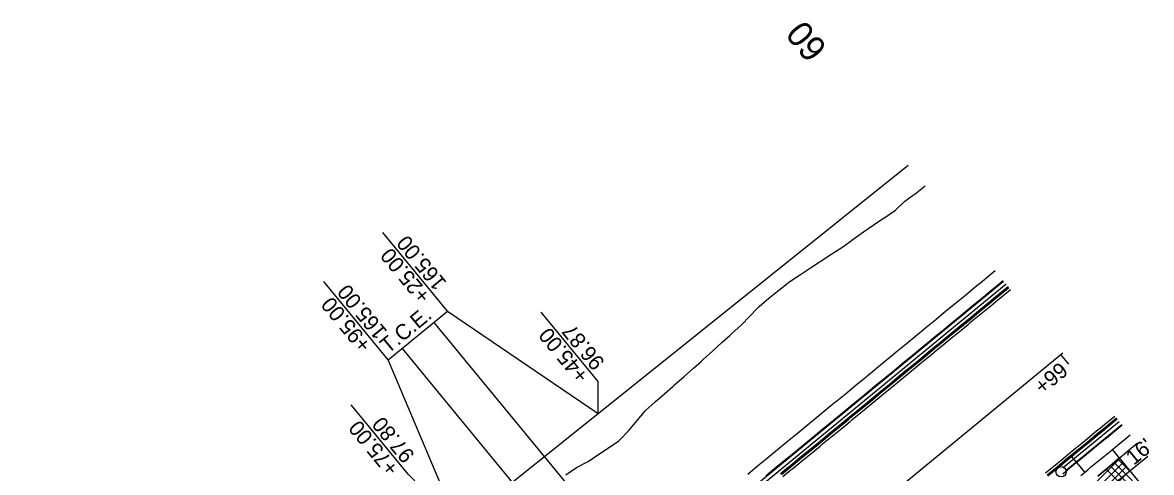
# Model space of a CAD drawing. Extents: x 1147550 to 1149124, y 2017436 to 2018779.
# Drawn here: x 1148677.5 to 1149118, y 2018603.7 to 2018779.4 of the extents above; entities that cross this region are included whole.
import ezdxf

# ---------------------------------------------------------------- set-up
doc = ezdxf.new("R2010")
doc.units = 0
for name, color, linetype in [('S_EDGE_CONCRETE', 7, 'Continuous'), ('S_HEADWALL', 7, 'Continuous'), ('S_IRON_PIN', 7, 'Continuous'), ('S_IRON_PIN_ANNOT', 7, 'Continuous'), ('S_LANDSCAPING', 7, 'Continuous'), ('S_MAILBOX', 7, 'Continuous'), ('S_RDW_PT_SYM', 7, 'Continuous'), ('S_SECONDARY_CTL', 7, 'Continuous'), ('S_TELEPHONE_UTILITIES', 7, 'Continuous'), ('S_TELEPHONE_UTILITIES_ANNOT', 7, 'Continuous')]:
    doc.layers.add(name, color=color, linetype=linetype)

msp = doc.modelspace()

# ---------------------------------------------------------------- linework, layer by layer
at = {"layer": 'S_EDGE_CONCRETE'}
msp.add_line((1148677.53, 2018316.54), (1149083.36, 2018650.43), dxfattribs=at)
at = {"layer": 'S_HEADWALL'}
for p, q in [((1148837.98, 2018662.21), (1148916.45, 2018566.84)), ((1148825.63, 2018652.05), (1148904.09, 2018556.68)), ((1149085.76, 2018645.93), (1149082.59, 2018649.79)), ((1149091.96, 2018603.77), (1149086.88, 2018609.94)), ((1149117.99, 2018594.17), (1149102.78, 2018612.66))]:
    msp.add_line(p, q, dxfattribs=at)
at = {"layer": 'S_IRON_PIN'}
msp.add_lwpolyline([(1148847.47, 2018583), (1148820.22, 2018647.6), (1148843.39, 2018666.66), (1148902.12, 2018626.75)], dxfattribs=at)
at = {"layer": 'S_IRON_PIN_ANNOT'}
for p, q in [((1148922.38, 2018425.84), (1149105.68, 2018609.13)), ((1149104.93, 2018608.83), (1149110.52, 2018603.24)), ((1148923.66, 2018424.29), (1149106.95, 2018607.58)), ((1148924.94, 2018422.74), (1149108.23, 2018606.03)), ((1148926.21, 2018421.18), (1149109.51, 2018604.48)), ((1149100.34, 2018604.95), (1149114.52, 2018590.76)), ((1149101.87, 2018606.24), (1149115.95, 2018592.16)), ((1149103.4, 2018607.54), (1149117.37, 2018593.57))]:
    msp.add_line(p, q, dxfattribs=at)
msp.add_lwpolyline([(1149117.96, 2018594.21), (1149105.52, 2018609.33), (1149100.94, 2018605.45), (1149097.12, 2018602.22)], dxfattribs=at)
at = {"layer": 'S_LANDSCAPING'}
for points in [[(1148843.39, 2018666.66), (1148818.14, 2018697.35)], [(1148820.22, 2018647.6), (1148795.02, 2018678.23)], [(1148902.12, 2018626.75), (1148902.12, 2018639.23), (1148879.88, 2018666.26)], [(1148847.47, 2018583), (1148827.96, 2018602.98), (1148805.73, 2018630.01)]]:
    msp.add_lwpolyline(points, dxfattribs=at)
at = {"layer": 'S_MAILBOX'}
msp.add_line((1148835.76, 2018573.62), (1149023.13, 2018723.63), dxfattribs=at)
msp.add_lwpolyline([(1149101.12, 2018597.36), (1149116.55, 2018610.09)], dxfattribs=at)
at = {"layer": 'S_SECONDARY_CTL'}
for points in [[(1148889.45, 2018602.8), (1148893.62, 2018605.6), (1148897.97, 2018607.87), (1148898.16, 2018607.96), (1148902.33, 2018610.75), (1148906.5, 2018613.56), (1148910.14, 2018616.08), (1148910.61, 2018616.44), (1148914.07, 2018620.1), (1148917.34, 2018624), (1148920.17, 2018627.38), (1148920.63, 2018627.86), (1148924.38, 2018631.18), (1148928.12, 2018634.5), (1148931.32, 2018637.33), (1148931.87, 2018637.82), (1148935.61, 2018641.14), (1148939.35, 2018644.45), (1148942.37, 2018647.16), (1148943.1, 2018647.77), (1148946.8, 2018651.14), (1148950.51, 2018654.5), (1148953.45, 2018657.17), (1148954.21, 2018657.87), (1148957.92, 2018661.24), (1148961.41, 2018664.86), (1148964.09, 2018667.7), (1148964.87, 2018668.53), (1148968.69, 2018671.76), (1148972.62, 2018674.85), (1148975.6, 2018677.18), (1148976.56, 2018677.93), (1148980.71, 2018680.75), (1148984.92, 2018683.51), (1148988.01, 2018685.56), (1148989.12, 2018686.28), (1148993.34, 2018689.01), (1148997.52, 2018691.81), (1149000.46, 2018693.91), (1149001.59, 2018694.72), (1149005.67, 2018697.63), (1149009.83, 2018700.45), (1149012.73, 2018702.47), (1149013.97, 2018703.28), (1149018.16, 2018706.06), (1149021.72, 2018709.61), (1149024.63, 2018711.69), (1149025.79, 2018712.52), (1149029.74, 2018715.6)], [(1149097.12, 2018602.22), (1149100.94, 2018605.45), (1149104.75, 2018608.68), (1149107.48, 2018610.99), (1149108.57, 2018611.91), (1149112.4, 2018615.13)]]:
    msp.add_lwpolyline(points, dxfattribs=at)
at = {"layer": 'S_TELEPHONE_UTILITIES'}
for points in [[(1148960.46, 2018603.06), (1148964.32, 2018606.23), (1148968.19, 2018609.41), (1148971.31, 2018611.98), (1148972.05, 2018612.59), (1148975.91, 2018615.76), (1148979.77, 2018618.94), (1148982.83, 2018621.46), (1148983.63, 2018622.12), (1148987.49, 2018625.29), (1148991.35, 2018628.47), (1148994.34, 2018630.93), (1148995.21, 2018631.65), (1148999.08, 2018634.82), (1149002.94, 2018638), (1149005.86, 2018640.4), (1149006.8, 2018641.18), (1149010.66, 2018644.35), (1149014.52, 2018647.53), (1149017.37, 2018649.88), (1149018.38, 2018650.71), (1149022.24, 2018653.88), (1149026.1, 2018657.06), (1149028.89, 2018659.36), (1149029.96, 2018660.24), (1149033.83, 2018663.41), (1149037.69, 2018666.59), (1149040.41, 2018668.83), (1149041.55, 2018669.77), (1149045.41, 2018672.94), (1149049.27, 2018676.12), (1149052.03, 2018678.39), (1149053.13, 2018679.3), (1149056.99, 2018682.47)], [(1148967.5, 2018602.37), (1148971.36, 2018605.55), (1148974.49, 2018608.12), (1148975.22, 2018608.73), (1148979.08, 2018611.9), (1148982.95, 2018615.08), (1148986.01, 2018617.6), (1148986.81, 2018618.26), (1148990.67, 2018621.43), (1148994.53, 2018624.61), (1148997.52, 2018627.07), (1148998.39, 2018627.79), (1149002.25, 2018630.96), (1149006.11, 2018634.14), (1149009.04, 2018636.54), (1149009.97, 2018637.32), (1149013.84, 2018640.49), (1149017.7, 2018643.67), (1149020.55, 2018646.02), (1149021.56, 2018646.85), (1149025.42, 2018650.02), (1149029.28, 2018653.2), (1149032.07, 2018655.49), (1149033.14, 2018656.38), (1149037, 2018659.55), (1149040.86, 2018662.73), (1149043.59, 2018664.97), (1149044.72, 2018665.91), (1149048.59, 2018669.08), (1149052.45, 2018672.26), (1149055.21, 2018674.53), (1149056.31, 2018675.44), (1149060.17, 2018678.61)], [(1148973.27, 2018603.23), (1148976.39, 2018605.8), (1148977.13, 2018606.41), (1148980.99, 2018609.59), (1148984.85, 2018612.76), (1148987.91, 2018615.28), (1148988.71, 2018615.94), (1148992.57, 2018619.12), (1148996.44, 2018622.29), (1148999.43, 2018624.75), (1149000.3, 2018625.47), (1149004.16, 2018628.65), (1149008.02, 2018631.82), (1149010.94, 2018634.23), (1149011.88, 2018635), (1149015.74, 2018638.18), (1149019.6, 2018641.35), (1149022.46, 2018643.7), (1149023.46, 2018644.53), (1149027.32, 2018647.71), (1149031.19, 2018650.88), (1149033.98, 2018653.18), (1149035.05, 2018654.06), (1149038.91, 2018657.24), (1149042.77, 2018660.41), (1149045.49, 2018662.65), (1149046.63, 2018663.59), (1149050.49, 2018666.77), (1149054.35, 2018669.94), (1149057.11, 2018672.21), (1149058.21, 2018673.12), (1149062.08, 2018676.3)], [(1148973.59, 2018602.85), (1148976.71, 2018605.42), (1148977.45, 2018606.02), (1148981.31, 2018609.2), (1148985.17, 2018612.38), (1148988.23, 2018614.89), (1148989.03, 2018615.55), (1148992.89, 2018618.73), (1148996.75, 2018621.91), (1148999.74, 2018624.37), (1149000.61, 2018625.08), (1149004.48, 2018628.26), (1149008.34, 2018631.44), (1149011.26, 2018633.84), (1149012.2, 2018634.61), (1149016.06, 2018637.79), (1149019.92, 2018640.97), (1149022.77, 2018643.31), (1149023.78, 2018644.14), (1149027.64, 2018647.32), (1149031.5, 2018650.5), (1149034.29, 2018652.79), (1149035.36, 2018653.67), (1149039.23, 2018656.85), (1149043.09, 2018660.03), (1149045.81, 2018662.27), (1149046.95, 2018663.2), (1149050.81, 2018666.38), (1149054.67, 2018669.56), (1149057.43, 2018671.83), (1149058.53, 2018672.73), (1149062.39, 2018675.91)], [(1148974.22, 2018602.07), (1148977.35, 2018604.65), (1148978.08, 2018605.25), (1148981.94, 2018608.43), (1148985.81, 2018611.6), (1148988.87, 2018614.12), (1148989.67, 2018614.78), (1148993.53, 2018617.96), (1148997.39, 2018621.13), (1149000.38, 2018623.6), (1149001.25, 2018624.31), (1149005.11, 2018627.49), (1149008.97, 2018630.66), (1149011.89, 2018633.07), (1149012.83, 2018633.84), (1149016.69, 2018637.02), (1149020.56, 2018640.19), (1149023.41, 2018642.54), (1149024.42, 2018643.37), (1149028.28, 2018646.55), (1149032.14, 2018649.72), (1149034.93, 2018652.02), (1149036, 2018652.9), (1149039.86, 2018656.08), (1149043.72, 2018659.25), (1149046.44, 2018661.49), (1149047.58, 2018662.43), (1149051.44, 2018665.61), (1149055.31, 2018668.78), (1149058.07, 2018671.05), (1149059.17, 2018671.96), (1149063.03, 2018675.14)], [(1149076.66, 2018603.48), (1149080.52, 2018606.65), (1149084.38, 2018609.83), (1149087.11, 2018612.07), (1149088.25, 2018613.01), (1149092.11, 2018616.18), (1149095.97, 2018619.36), (1149098.73, 2018621.63), (1149099.83, 2018622.54), (1149103.69, 2018625.71)], [(1149077.3, 2018602.71), (1149081.16, 2018605.88), (1149085.02, 2018609.06), (1149087.74, 2018611.3), (1149088.88, 2018612.24), (1149092.74, 2018615.41), (1149096.6, 2018618.59), (1149099.36, 2018620.86), (1149100.46, 2018621.77), (1149104.33, 2018624.94)], [(1149077.61, 2018602.32), (1149081.48, 2018605.5), (1149085.34, 2018608.67), (1149088.06, 2018610.91), (1149089.2, 2018611.85), (1149093.06, 2018615.03), (1149096.92, 2018618.2), (1149099.68, 2018620.47), (1149100.78, 2018621.38), (1149104.64, 2018624.56)], [(1149083.38, 2018603.18), (1149087.24, 2018606.36), (1149089.97, 2018608.6), (1149091.1, 2018609.53), (1149094.97, 2018612.71), (1149098.83, 2018615.89), (1149101.59, 2018618.16), (1149102.69, 2018619.06), (1149106.55, 2018622.24)], [(1149090.42, 2018602.5), (1149093.14, 2018604.73), (1149094.28, 2018605.67), (1149098.14, 2018608.85), (1149102, 2018612.03), (1149104.76, 2018614.3), (1149105.86, 2018615.2), (1149109.73, 2018618.38)]]:
    msp.add_lwpolyline(points, dxfattribs=at)
at = {"layer": 'S_TELEPHONE_UTILITIES_ANNOT'}
for p, q in [((1148876.42, 2018527.12), (1149060.33, 2018678.42)), ((1148876.42, 2018527.12), (1149060.33, 2018678.42)), ((1148877.38, 2018525.96), (1149061.28, 2018677.26)), ((1148877.38, 2018525.96), (1149061.28, 2018677.26)), ((1149083.7, 2018605.71), (1149105.44, 2018623.59)), ((1149083.7, 2018605.71), (1149105.44, 2018623.59)), ((1149084.66, 2018604.55), (1149106.39, 2018622.43)), ((1149084.66, 2018604.55), (1149106.39, 2018622.43))]:
    msp.add_line(p, q, dxfattribs=at)
msp.add_circle((1149082.75, 2018603.95), 2, dxfattribs=at)

# ---------------------------------------------------------------- texts
at = {"layer": 'S_HEADWALL'}
for s, p in [('+99', (1149075.46, 2018633.83)), ("16'", (1149111.08, 2018606.23))]:
    msp.add_text(s, height=6, rotation=39.4453, dxfattribs=at).set_placement(p)
at = {"layer": 'S_IRON_PIN'}
msp.add_text('T.C.E.', height=6, rotation=39.4453, dxfattribs=at).set_placement((1148820.14, 2018649.86))
at = {"layer": 'S_LANDSCAPING'}
for s, p in [('165.00', (1148843.24, 2018677.86)), ('+25.00', (1148837.06, 2018672.78)), ('165.00', (1148820.12, 2018658.74)), ('+95.00', (1148813.94, 2018653.66)), ('+45.00', (1148898.81, 2018641.69)), ('96.87', (1148904.98, 2018646.77)), ('+75.00', (1148824.65, 2018605.43)), ('97.80', (1148830.83, 2018610.51))]:
    msp.add_text(s, height=6, rotation=129.4453, dxfattribs=at).set_placement(p)
at = {"layer": 'S_RDW_PT_SYM'}
msp.add_text('60', height=10, rotation=129.4453, dxfattribs=at).set_placement((1148991.92, 2018769.44))

doc.saveas('drawing.dxf')
